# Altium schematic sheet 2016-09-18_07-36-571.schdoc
size 557 x 193 mm; SheetNumber: 1; SheetTotal: 1
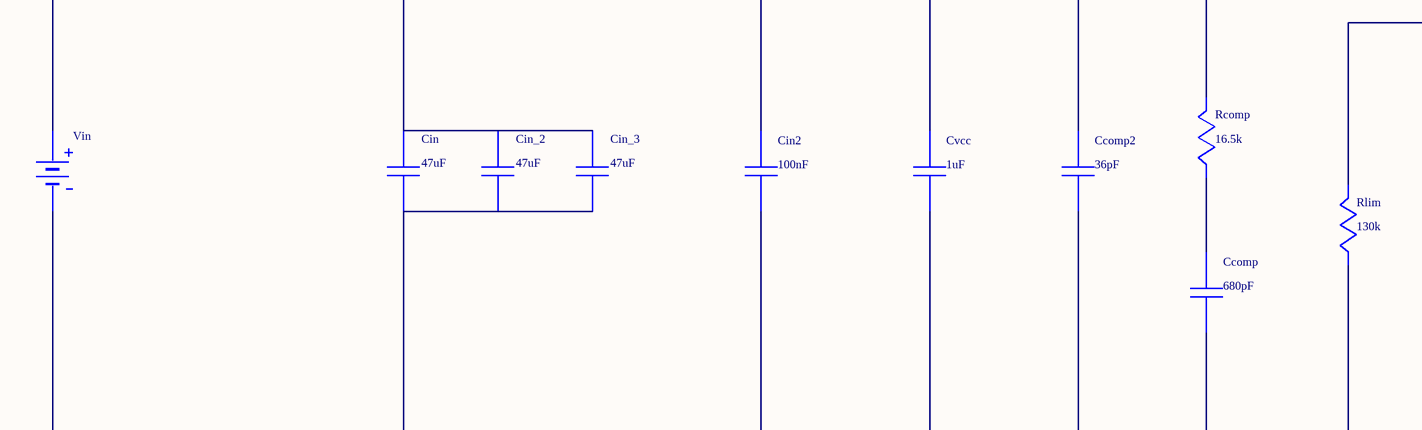
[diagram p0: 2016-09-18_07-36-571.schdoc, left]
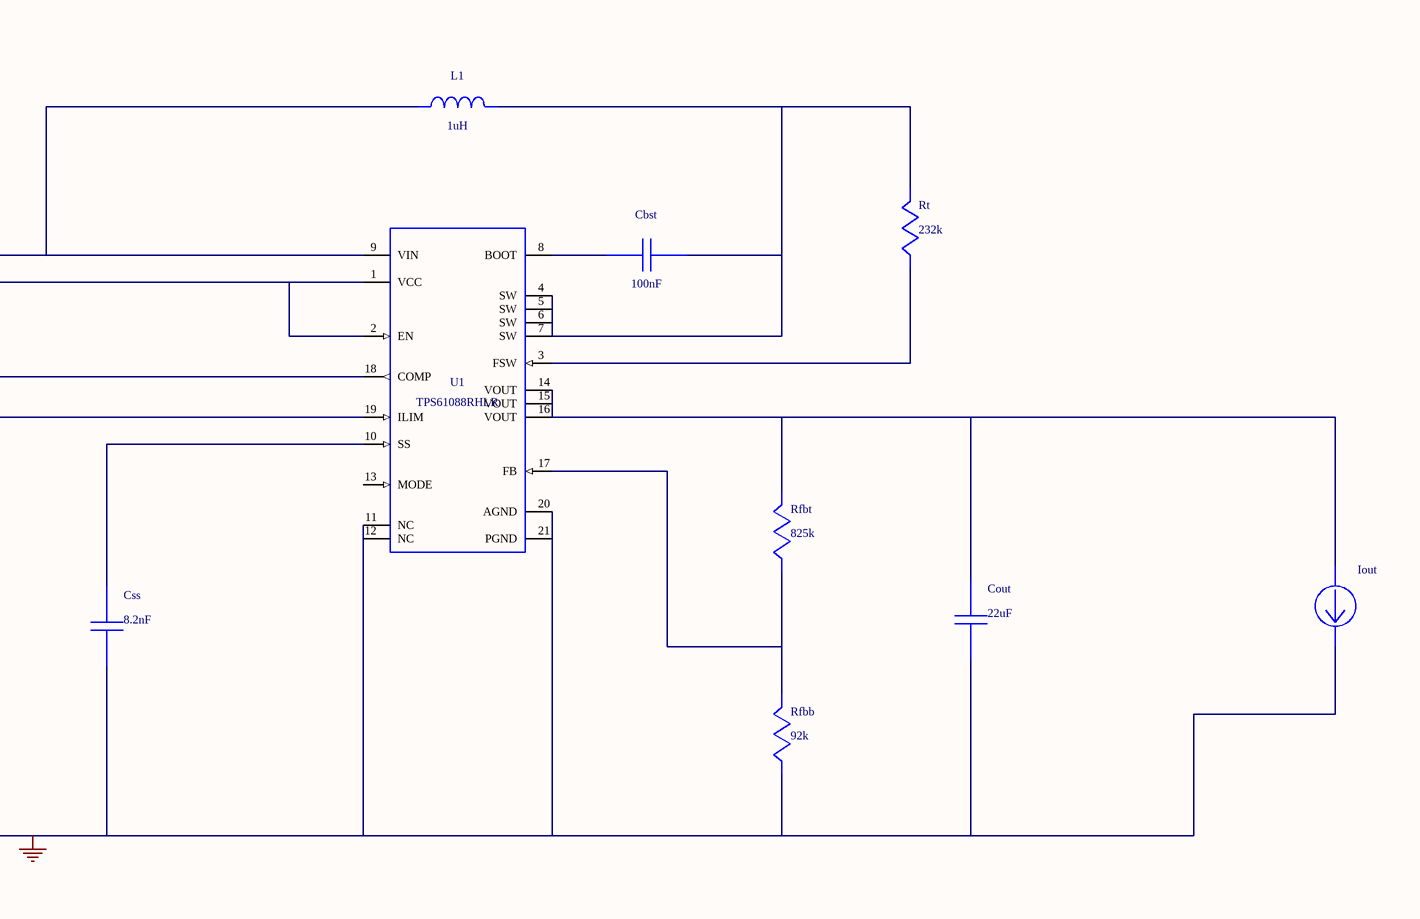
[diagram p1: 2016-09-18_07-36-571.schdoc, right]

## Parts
Cbst  value 100nF  (hidden comment: 08053C104KAT2A)
Ccomp  value 680pF  (hidden comment: GRM033R71C681KA01D)
Ccomp2  value 36pF  (hidden comment: C0603C0G1E360G)
Cin  value 47uF  (hidden comment: C3216X5R1E476M160AC)
Cin2  value 100nF  (hidden comment: GRM155R61C104KA88D)
Cin_2  value 47uF  (hidden comment: C3216X5R1E476M160AC)
Cin_3  value 47uF  (hidden comment: C3216X5R1E476M160AC)
Cout  value 22uF  (hidden comment: GRM32ER61E226KE15L)
Css  value 8.2nF  (hidden comment: GRM155R71C822KA01D)
Cvcc  value 1uF  (hidden comment: GRM188R61A105KA61D)
Iout  WB_CURRENT_LOAD  (value not drawn)
L1  value 1uH  (hidden comment: VLP8040T-1R0N)
Rcomp  value 16.5k  (hidden comment: CRCW040216K5FKED)
Rfbb  value 92k  (hidden comment: RT0805BRD0792KL)
Rfbt  value 825k  (hidden comment: CRCW0402825KFKED)
Rlim  value 130k  (hidden comment: CRCW0402130KFKED)
Rt  value 232k  (hidden comment: CRCW0402232KFKED)
U1  TPS61088RHLR
Vin  WB_BATTERY  (value not drawn)

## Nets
0: Ccomp.2 Ccomp2.2 Cin.2 Cin2.2 Cin_2.2 Cin_3.2 Cout.2 Css.2 Cvcc.2 Iout.2(-) Rfbb.2 Rlim.2 U1.11(NC) U1.12(NC) U1.20(AGND) U1.21(PGND) Vin.2(-)
NetCbst_1: Cbst.1 U1.8(BOOT)
NetCbst_2: Cbst.2 L1.2 Rt.1 U1.4(SW) U1.5(SW) U1.6(SW) U1.7(SW)
NetCcomp2_1: Ccomp2.1 Rcomp.1 U1.18(COMP)
NetCcomp_1: Ccomp.1 Rcomp.2
NetCin_1: Cin.1 Cin2.1 Cin_2.1 Cin_3.1 L1.1 U1.9(VIN) Vin.1(+)
NetCout_1: Cout.1 Iout.1(+) Rfbt.1 U1.14(VOUT) U1.15(VOUT) U1.16(VOUT)
NetCss_1: Css.1 U1.10(SS)
NetCvcc_1: Cvcc.1 U1.1(VCC) U1.2(EN)
NetRfbb_1: Rfbb.1 Rfbt.2 U1.17(FB)
NetRlim_1: Rlim.1 U1.19(ILIM)
NetRt_2: Rt.2 U1.3(FSW)

Not connected (* = marked no-connect by the designer): U1 13(MODE)

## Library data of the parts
Cbst = 08053C104KAT2A: Manufacturer Name: AVX
Ccomp = GRM033R71C681KA01D: GRM033R71C681KA0; Manufacturer Name: MuRata
Ccomp2 = C0603C0G1E360G: Manufacturer Name: TDK
Cin Cin_2 Cin_3 = C3216X5R1E476M160AC: C3216X5R1E476M16; Manufacturer Name: TDK
Cin2 = GRM155R61C104KA88D: GRM155R61C104KA8; Manufacturer Name: MuRata
Cout = GRM32ER61E226KE15L: GRM32ER61E226KE1; Manufacturer Name: MuRata
Css = GRM155R71C822KA01D: GRM155R71C822KA0; Manufacturer Name: MuRata
Cvcc = GRM188R61A105KA61D: GRM188R61A105KA6; Manufacturer Name: MuRata
L1 = VLP8040T-1R0N: Unknown; Manufacturer Name: TDK
Rcomp = CRCW040216K5FKED: Manufacturer Name: Vishay-Dale
Rfbb = RT0805BRD0792KL: Manufacturer Name: Yageo America
Rfbt = CRCW0402825KFKED: Manufacturer Name: Vishay-Dale
Rlim = CRCW0402130KFKED: Manufacturer Name: Vishay-Dale
Rt = CRCW0402232KFKED: Manufacturer Name: Vishay-Dale
U1 = TPS61088RHLR: Manufacturer Name: Texas Instruments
